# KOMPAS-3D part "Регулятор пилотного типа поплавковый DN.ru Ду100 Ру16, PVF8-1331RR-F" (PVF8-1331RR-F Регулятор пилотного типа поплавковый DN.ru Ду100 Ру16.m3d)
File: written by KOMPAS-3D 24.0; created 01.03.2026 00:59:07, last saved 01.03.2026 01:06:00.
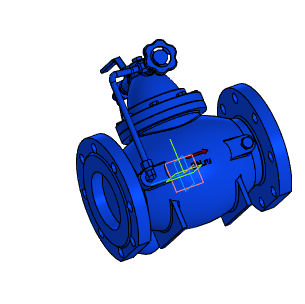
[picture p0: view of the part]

Document properties: Автор: R2D2; Полное имя файла: E:\Работа\Зайцев\PVF8-1331RR-F Регулятор пилотного типа поплавковый DN.ru Ду15-300\DN100\PVF8-1331RR-F Регулятор пилотного типа поплавковый DN.ru Ду100 Ру16.m3d

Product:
- Part/product: Регулятор пилотного типа поплавковый DN.ru Ду100 Ру16  | designation PVF8-1331RR-F
    Масса: 18
    Раздел спецификации: Прочие изделия
    Примечание: D230-24375
    additional columns: D230-24375

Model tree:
1. Операция без истории:3

Expressions: PVF8-1331RR-F
Referenced files in C:\Program Files\ASCON\KOMPAS-3D v24\Libs\EasySteel\: Rolled metal.kle, StandartSolutions.kle, DSTVProperties.lpt
Referenced files in C:\Program Files\ASCON\KOMPAS-3D v24\Templates\: Констр. чертеж А3 гориз. перв. лист.cdt
Referenced files in C:\Program Files\ASCON\KOMPAS-3D v24\Libs\EasySteel\BeltEndings\: 
Referenced files in C:\Program Files\ASCON\KOMPAS-3D v24\Libs\EasySteel\Punctures\: 
Referenced files in C:\Program Files\ASCON\KOMPAS-3D v24\Libs\EasySteel\Insulations\: 
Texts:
  Уголок равнополочный по ГОСТ 8509-93 (Спец)
  config2DpacketName
  config2DstdSizeID
  Констр. чертеж А3 гориз. перв. лист.cdt
  Болт ГОСТ 22353-77
  Шайба ГОСТ 22355-77
  Гайка ГОСТ 22354-77
  Нормальная пружинная шайба ГОСТ 6402-70 (исп. 1)
  SeaRox SL 436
